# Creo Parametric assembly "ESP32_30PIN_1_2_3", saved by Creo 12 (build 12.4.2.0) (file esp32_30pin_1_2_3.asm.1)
Units: Custom; MM, KILOGRAM, SECS

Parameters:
  PTC_WM_ITERATION = "0"
  PTC_WM_VERSION = "-.0"
  PTC_WM_LIFECYCLE_STATE = "In Work"
  PTC_WM_LIFECYCLE = "MO_CADDocument"
  PTC_WM_CREATED_BY = "Maximilian Roepper (Z0017RMS: MO)"
  PTC_WM_CREATED_ON = "18-Sep-26 11:36:42 AM"
  PTC_WM_MODIFIED_BY = "Maximilian Roepper (Z0017RMS: MO)"
  PTC_WM_MODIFIED_ON = "18-Sep-26 11:36:46 AM"
  PDMLINKNUMBER = "PDM000071454803"
  PTC_WM_NUMBER = "PDM000071454803"

Other parameters: WEIGHT, WEIGHT_FACTOR, WEIGHT_ADD, MC_ERRORS, SUPPLIER

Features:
  1. coordinate system
  2. imported feature
  3. component "ESP32_WROOM_32D_KITV1_CASING__1"

Other named items: DRW_VIEW_ORG, ROUGH-GROB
